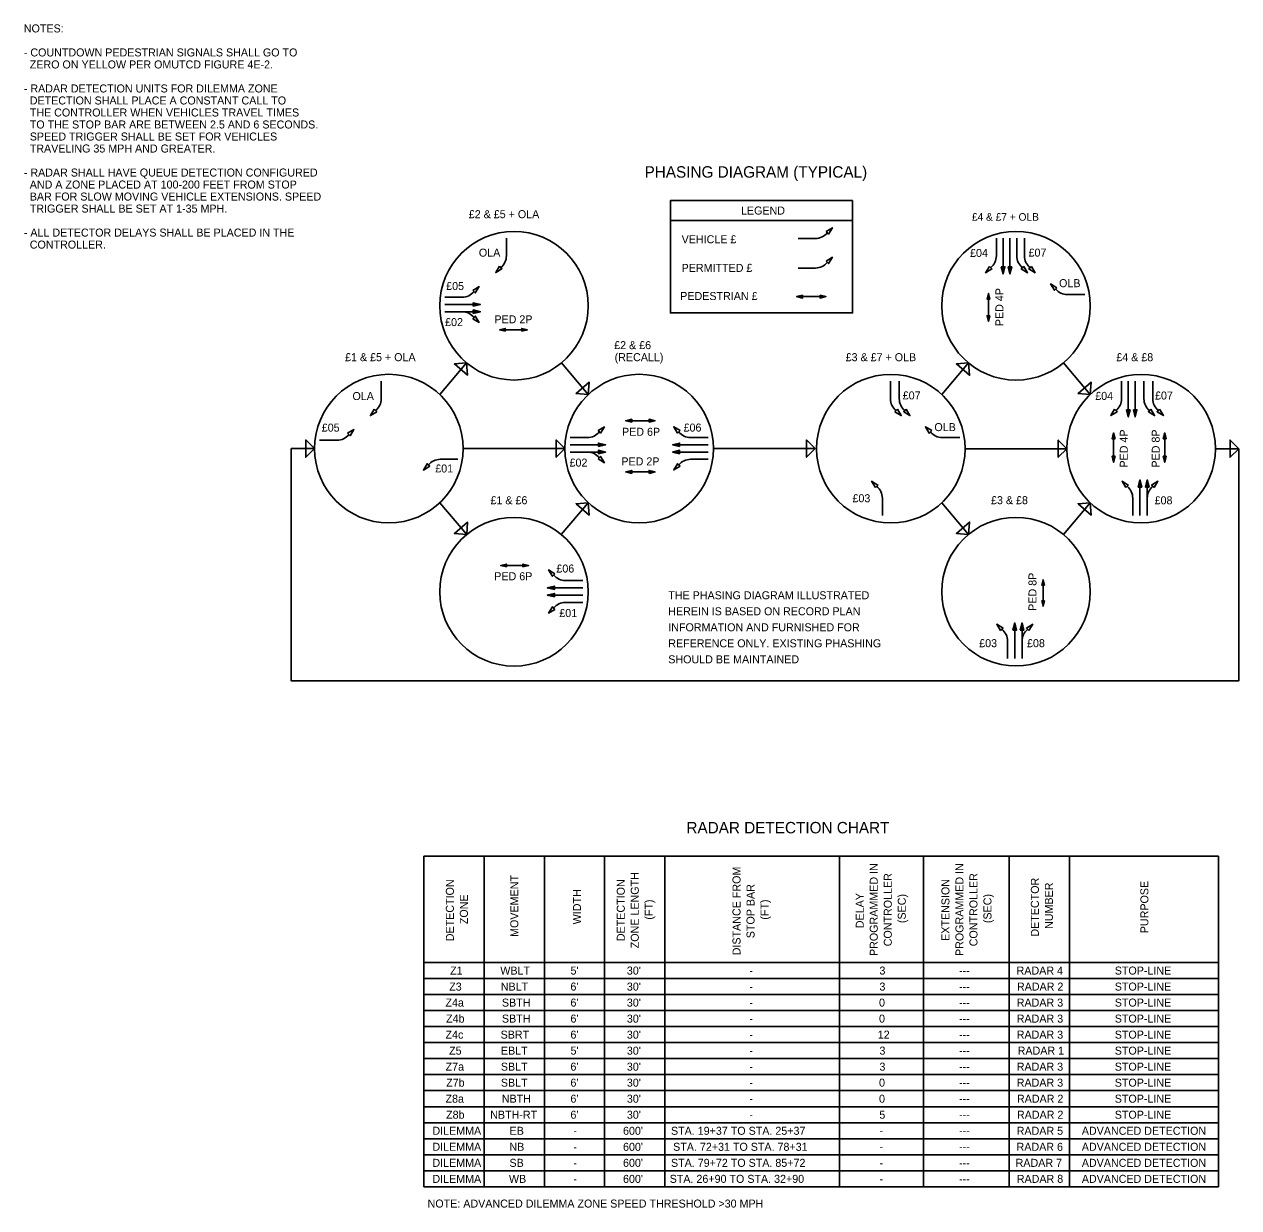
# Model space of a CAD drawing. Extents: x 680 to 2132, y 0 to 656.
# Drawn here: x 1377.8 to 1802.7, y 81 to 494.9 of the extents above; entities that cross this region are included whole.
import ezdxf

# ---------------------------------------------------------------- set-up
doc = ezdxf.new("R2010")
doc.units = 0
for name, color, linetype in [('SH_Data', 7, 'Continuous'), ('SH_Text', 7, 'Continuous'), ('ST_Text', 7, 'Continuous')]:
    doc.layers.add(name, color=color, linetype=linetype)

msp = doc.modelspace()

# ---------------------------------------------------------------- linework, layer by layer
at = {"layer": 'SH_Data'}
for p, q in [((1603.79, 426.28), (1667.83, 426.28)), ((1546.48, 420.09), (1546.48, 413.98)), ((1648.51, 420.01), (1654.62, 420.01)), ((1717.88, 420.06), (1717.88, 413.95)), ((1720.22, 407.61), (1720.22, 420.06)), ((1722.63, 407.61), (1722.63, 420.06)), ((1725.04, 420.06), (1725.04, 413.95)), ((1727.7, 420.06), (1727.7, 413.95)), ((1648.51, 409.67), (1654.62, 409.67)), ((1524.93, 399.45), (1531.04, 399.45)), ((1658.28, 399.71), (1648.02, 399.71)), ((1715.16, 391.03), (1715.16, 400.78)), ((1748.85, 400.36), (1742.74, 400.36)), ((1537.38, 396.92), (1524.93, 396.92)), ((1524.93, 394.38), (1531.04, 394.38)), ((1537.38, 394.38), (1524.93, 394.38)), ((1544.09, 388.03), (1553.84, 388.03)), ((1532.57, 376.48), (1523.14, 365.44)), ((1575.14, 365.44), (1565.71, 376.48)), ((1708.16, 376.46), (1698.76, 365.45)), ((1750.75, 365.44), (1741.33, 376.46)), ((1502.68, 370.09), (1502.68, 363.98)), ((1680.84, 370.09), (1680.84, 363.98)), ((1683.92, 370.09), (1683.92, 363.98)), ((1761.69, 370.09), (1761.69, 363.98)), ((1764.03, 357.63), (1764.03, 370.09)), ((1766.43, 357.63), (1766.43, 370.09)), ((1769.51, 370.09), (1769.51, 363.98)), ((1772.59, 370.09), (1772.59, 363.98)), ((1588.23, 356.25), (1598.49, 356.25)), ((1481.12, 349.46), (1487.23, 349.46)), ((1568.73, 350.39), (1574.84, 350.39)), ((1617.04, 350.39), (1610.93, 350.39)), ((1705.07, 350.39), (1698.96, 350.39)), ((1758.91, 341.75), (1758.91, 352.02)), ((1776.81, 341.75), (1776.81, 352.02)), ((1566.95, 346.51), (1531.33, 346.51)), ((1581.19, 347.85), (1568.73, 347.85)), ((1581.19, 345.32), (1568.73, 345.32)), ((1568.73, 345.32), (1574.84, 345.31)), ((1604.59, 347.85), (1617.04, 347.85)), ((1604.59, 345.32), (1617.04, 345.32)), ((1654.55, 346.51), (1618.93, 346.51)), ((1742.56, 346.5), (1706.96, 346.5)), ((1529.44, 342.78), (1523.33, 342.78)), ((1617.04, 342.78), (1610.93, 342.78)), ((1588.23, 338.36), (1598.49, 338.36)), ((1768.13, 335.55), (1768.13, 323.09)), ((1770.66, 335.55), (1770.66, 323.09)), ((1532.59, 316.5), (1523.14, 327.57)), ((1575.14, 327.57), (1565.69, 316.5)), ((1678, 323.09), (1678, 329.2)), ((1708.18, 316.52), (1698.76, 327.56)), ((1750.75, 327.56), (1741.32, 316.52)), ((1765.59, 323.09), (1765.59, 329.2)), ((1544.48, 305.64), (1554.23, 305.64)), ((1560.78, 297.81), (1573.24, 297.81)), ((1573.24, 300.35), (1567.13, 300.35)), ((1734.23, 291.39), (1734.23, 300.65)), ((1560.78, 295.27), (1573.24, 295.27)), ((1573.24, 292.74), (1567.13, 292.74)), ((1724.32, 285.54), (1724.32, 273.08)), ((1726.86, 285.54), (1726.86, 273.08)), ((1721.79, 273.08), (1721.79, 279.19)), ((1726.86, 279.05), (1726.86, 279.19))]:
    msp.add_line(p, q, dxfattribs=at)
for points in [[(1667.6, 433.28), (1603.83, 433.28), (1603.83, 393.95), (1667.6, 393.95)], [(1658.31, 422.43), (1660.52, 423.76), (1659.19, 421.55)], [(1658.31, 412.09), (1660.52, 413.42), (1659.19, 411.21)], [(1544.06, 410.29), (1542.73, 408.08), (1544.94, 409.41)], [(1715.46, 410.26), (1714.14, 408.05), (1716.35, 409.38)], [(1719.6, 410.11), (1720.22, 407.61), (1720.85, 410.11)], [(1722, 410.11), (1722.63, 407.61), (1723.26, 410.11)], [(1727.46, 410.26), (1728.78, 408.05), (1726.57, 409.38)], [(1730.12, 410.26), (1731.45, 408.05), (1729.24, 409.38)], [(1739.05, 402.78), (1736.84, 404.11), (1738.17, 401.9)], [(1534.73, 401.87), (1536.94, 403.2), (1535.61, 400.99)], [(1650.1, 400.23), (1648.02, 399.71), (1650.1, 399.19)], [(1656.2, 400.23), (1658.28, 399.71), (1656.2, 399.19)], [(1715.65, 398.8), (1715.16, 400.78), (1714.66, 398.8)], [(1534.88, 396.29), (1537.38, 396.92), (1534.88, 397.54)], [(1534.72, 391.96), (1536.94, 390.63), (1535.61, 392.84)], [(1534.88, 393.76), (1537.38, 394.38), (1534.88, 395.01)], [(1715.65, 393.01), (1715.16, 391.03), (1714.66, 393.01)], [(1546.07, 387.54), (1544.09, 388.03), (1546.07, 388.53)], [(1551.86, 387.54), (1553.84, 388.03), (1551.86, 388.53)], [(1532.57, 376.48), (1528.29, 376.14), (1532.9, 372.21)], [(1708.16, 376.46), (1703.89, 376.12), (1708.5, 372.19)], [(1575.14, 365.44), (1570.86, 365.78), (1575.47, 369.72)], [(1750.75, 365.44), (1746.47, 365.77), (1751.08, 369.71)], [(1500.26, 360.29), (1498.93, 358.08), (1501.14, 359.41)], [(1683.26, 360.29), (1684.59, 358.08), (1682.38, 359.41)], [(1686.34, 360.29), (1687.66, 358.08), (1685.46, 359.41)], [(1759.26, 360.29), (1757.94, 358.08), (1760.15, 359.41)], [(1763.4, 360.13), (1764.03, 357.63), (1764.65, 360.13)], [(1765.81, 360.13), (1766.43, 357.63), (1767.06, 360.13)], [(1771.93, 360.29), (1773.25, 358.08), (1771.05, 359.41)], [(1775.01, 360.29), (1776.33, 358.08), (1774.12, 359.41)], [(1490.92, 351.88), (1493.14, 353.2), (1491.81, 350.99)], [(1578.53, 352.81), (1580.74, 354.13), (1579.41, 351.93)], [(1590.31, 355.73), (1588.23, 356.25), (1590.31, 356.77)], [(1596.41, 355.73), (1598.49, 356.25), (1596.41, 356.77)], [(1607.25, 352.81), (1605.03, 354.14), (1606.36, 351.93)], [(1695.27, 352.81), (1693.06, 354.13), (1694.39, 351.92)], [(1479.34, 346.51), (1476.31, 349.54), (1476.31, 343.48)], [(1566.95, 346.51), (1563.92, 349.54), (1563.92, 343.48)], [(1578.69, 347.23), (1581.19, 347.85), (1578.69, 348.48)], [(1607.09, 347.23), (1604.59, 347.85), (1607.09, 348.48)], [(1654.55, 346.51), (1651.52, 349.54), (1651.52, 343.48)], [(1742.56, 346.5), (1739.53, 349.53), (1739.53, 343.47)], [(1759.43, 349.94), (1758.91, 352.02), (1758.39, 349.94)], [(1777.33, 349.94), (1776.81, 352.02), (1776.29, 349.94)], [(1802.66, 346.5), (1799.63, 349.53), (1799.63, 343.47)], [(1578.69, 344.69), (1581.19, 345.32), (1578.69, 345.94)], [(1607.09, 344.69), (1604.59, 345.32), (1607.09, 345.94)], [(1519.64, 340.36), (1517.43, 339.03), (1518.76, 341.24)], [(1578.53, 342.89), (1580.74, 341.57), (1579.41, 343.78)], [(1607.25, 340.36), (1605.03, 339.04), (1606.36, 341.24)], [(1759.43, 343.84), (1758.91, 341.75), (1758.39, 343.84)], [(1777.33, 343.84), (1776.81, 341.75), (1776.29, 343.84)], [(1590.31, 337.84), (1588.23, 338.36), (1590.31, 338.88)], [(1596.41, 337.84), (1598.49, 338.36), (1596.41, 338.88)], [(1675.58, 332.89), (1674.26, 335.1), (1676.47, 333.77)], [(1763.17, 332.89), (1761.84, 335.1), (1764.05, 333.77)], [(1767.5, 333.05), (1768.13, 335.55), (1768.75, 333.05)], [(1770.04, 333.05), (1770.66, 335.55), (1771.29, 333.05)], [(1773.08, 332.89), (1774.41, 335.1), (1772.2, 333.77)], [(1575.14, 327.57), (1570.86, 327.23), (1575.47, 323.29)], [(1750.75, 327.56), (1746.47, 327.23), (1751.08, 323.29)], [(1532.59, 316.5), (1528.31, 316.84), (1532.92, 320.78)], [(1708.18, 316.52), (1703.91, 316.86), (1708.52, 320.8)], [(1546.46, 305.15), (1544.48, 305.64), (1546.46, 306.14)], [(1552.25, 305.15), (1554.23, 305.64), (1552.25, 306.14)], [(1563.44, 302.77), (1561.23, 304.09), (1562.56, 301.89)], [(1563.28, 297.19), (1560.78, 297.81), (1563.28, 298.44)], [(1734.7, 298.77), (1734.23, 300.65), (1733.76, 298.77)], [(1563.28, 294.65), (1560.78, 295.27), (1563.28, 295.9)], [(1734.7, 293.27), (1734.23, 291.39), (1733.76, 293.27)], [(1563.44, 290.31), (1561.23, 288.99), (1562.56, 291.2)], [(1719.37, 282.88), (1718.04, 285.09), (1720.25, 283.76)], [(1723.7, 283.04), (1724.32, 285.54), (1724.95, 283.04)], [(1726.23, 283.04), (1726.86, 285.54), (1727.48, 283.04)], [(1729.28, 282.88), (1730.6, 285.09), (1728.4, 283.76)]]:
    msp.add_lwpolyline(points, close=True, dxfattribs=at)
msp.add_lwpolyline([(1794.54, 346.5), (1802.66, 346.5), (1802.66, 265.28), (1479.34, 265.28), (1471.22, 265.28), (1471.22, 346.51), (1479.34, 346.51)], dxfattribs=at)
for centre in [(1549.14, 396.5), (1724.75, 396.48), (1505.34, 346.51), (1592.94, 346.51), (1680.96, 346.5), (1768.55, 346.5), (1549.14, 296.46), (1724.75, 296.49)]:
    msp.add_circle(centre, 25.99, dxfattribs=at)
for centre, start, end in [((1654.62, 425.31), 270.0129, 321.2136), ((1541.18, 413.98), 308.7993, 0), ((1712.58, 413.95), 308.7993, 0), ((1730.34, 413.95), 180, 231.2007), ((1733, 413.95), 180, 231.2007), ((1654.62, 414.97), 270, 321.2007), ((1531.04, 404.75), 270, 321.2007), ((1742.74, 405.66), 218.7864, 269.9871), ((1531.04, 389.08), 38.7864, 89.9871), ((1497.38, 363.98), 308.7993, 0), ((1686.14, 363.98), 180, 231.2007), ((1689.22, 363.98), 180, 231.2007), ((1756.38, 363.98), 308.7993, 0), ((1774.81, 363.98), 180, 231.2007), ((1777.89, 363.98), 180, 231.2007), ((1487.23, 354.76), 270, 321.2007), ((1574.84, 355.69), 270, 321.2007), ((1610.94, 355.69), 218.7864, 269.9871), ((1698.96, 355.69), 218.7864, 269.9871), ((1574.84, 340.01), 38.7864, 89.9871), ((1523.33, 337.48), 90.0129, 141.2136), ((1610.93, 337.48), 90, 141.2007), ((1672.7, 329.2), 360, 51.2007), ((1760.29, 329.2), 360, 51.2007), ((1775.96, 329.2), 128.7993, 178.779), ((1567.13, 305.65), 218.7864, 269.9871), ((1567.13, 287.44), 90.0129, 141.2136), ((1716.49, 279.19), 360, 51.2007), ((1732.16, 279.19), 128.7993, 180)]:
    msp.add_arc(centre, 5.3, start, end, dxfattribs=at)
at = {"layer": 'ST_Text'}
for p, q in [((1517.6, 204.01), (1795.54, 204.01)), ((1517.6, 204.01), (1517.6, 88.34)), ((1538.69, 204.01), (1538.69, 88.34)), ((1559.77, 204.01), (1559.77, 88.34)), ((1580.85, 204.01), (1580.85, 110.77)), ((1580.85, 204.01), (1580.85, 88.34)), ((1601.93, 204.01), (1601.93, 88.34)), ((1663.02, 204.01), (1663.02, 88.34)), ((1692.43, 204.01), (1692.43, 88.34)), ((1722.41, 204.01), (1722.41, 88.34)), ((1743.49, 204.01), (1743.49, 88.34)), ((1795.54, 204.01), (1795.54, 88.34)), ((1517.6, 166.8), (1795.54, 166.8)), ((1517.6, 161.2), (1795.54, 161.2)), ((1517.6, 155.6), (1795.54, 155.6)), ((1517.6, 150), (1795.54, 150)), ((1517.6, 144.4), (1795.54, 144.4)), ((1517.6, 138.8), (1795.54, 138.8)), ((1517.6, 133.2), (1795.54, 133.2)), ((1517.6, 127.6), (1795.54, 127.6)), ((1517.6, 121.98), (1795.54, 121.98)), ((1517.6, 116.38), (1795.54, 116.38)), ((1517.6, 110.77), (1795.54, 110.77)), ((1517.6, 105.17), (1795.54, 105.17)), ((1517.6, 99.55), (1795.54, 99.55)), ((1517.6, 93.95), (1795.54, 93.95)), ((1517.6, 88.34), (1795.54, 88.34))]:
    msp.add_line(p, q, dxfattribs=at)

# ---------------------------------------------------------------- texts
at = {"layer": 'SH_Text'}
for s, height, p in [('NOTES:', 2.8, (1377.66, 492.07)), ('- COUNTDOWN PEDESTRIAN SIGNALS SHALL GO TO ', 2.8, (1377.66, 483.67)), ('  ZERO ON YELLOW PER OMUTCD FIGURE 4E-2.', 2.8, (1377.66, 479.47)), ('- RADAR DETECTION UNITS FOR DILEMMA ZONE ', 2.8, (1377.66, 471.07)), ('  DETECTION SHALL PLACE A CONSTANT CALL TO ', 2.8, (1377.66, 466.87)), ('  THE CONTROLLER WHEN VEHICLES TRAVEL TIMES ', 2.8, (1377.66, 462.67)), ('  TO THE STOP BAR ARE BETWEEN 2.5 AND 6 SECONDS. ', 2.8, (1377.66, 458.47)), ('  SPEED TRIGGER SHALL BE SET FOR VEHICLES ', 2.8, (1377.66, 454.27)), ('  TRAVELING 35 MPH AND GREATER.', 2.8, (1377.66, 450.07)), ('- RADAR SHALL HAVE QUEUE DETECTION CONFIGURED ', 2.8, (1377.66, 441.67)), ('PHASING DIAGRAM (TYPICAL)', 4, (1594.82, 441.28)), ('  AND A ZONE PLACED AT 100-200 FEET FROM STOP ', 2.8, (1377.66, 437.47)), ('  BAR FOR SLOW MOVING VEHICLE EXTENSIONS. SPEED ', 2.8, (1377.66, 433.27)), ('  TRIGGER SHALL BE SET AT 1-35 MPH.', 2.8, (1377.66, 429.07)), ('£2 & £5 + OLA', 2.8, (1533.32, 427.1)), ('LEGEND', 2.8, (1628.55, 428.38)), ('£4 & £7 + OLB', 2.66, (1709.33, 426.22)), ('- ALL DETECTOR DELAYS SHALL BE PLACED IN THE ', 2.8, (1377.66, 420.67)), ('VEHICLE £', 2.8, (1607.78, 418.33)), ('  CONTROLLER.', 2.8, (1377.66, 416.47)), ('OLA', 2.8, (1536.85, 413.65)), ('£04', 2.8, (1708.68, 413.54)), ('£07', 2.8, (1729.14, 413.66)), ('PERMITTED £', 2.8, (1607.78, 408.33)), ('£05', 2.8, (1525.4, 401.98)), ('OLB', 2.8, (1739.82, 402.98)), ('PEDESTRIAN £', 2.8, (1607.29, 398.49)), ('£02', 2.8, (1525.04, 389.36)), ('PED 2P', 2.8, (1542.27, 390.33)), ('£2 & £6', 2.8, (1584.19, 381.3)), ('£1 & £5 + OLA', 2.8, (1490.05, 377.1)), ('(RECALL)', 2.8, (1584.35, 377.1)), ('£3 & £7 + OLB', 2.8, (1665.16, 377.09)), ('£4 & £8', 2.8, (1759.84, 377.09)), ('OLA', 2.8, (1492.63, 363.5)), ('£07', 2.8, (1685.13, 363.73)), ('£04', 2.8, (1752.48, 363.56)), ('£07', 2.8, (1773.39, 363.69)), ('£05', 2.8, (1481.89, 352.46)), ('PED 6P', 2.8, (1586.93, 351)), ('£06', 2.8, (1608.46, 352.48)), ('OLB', 2.8, (1696.21, 352.64)), ('£01', 2.8, (1521.59, 338.17)), ('£02', 2.8, (1568.57, 340.23)), ('PED 2P', 2.8, (1586.7, 340.65)), ('£1 & £6', 2.8, (1540.92, 327.06)), ('£03', 2.8, (1667.55, 327.76)), ('£3 & £8', 2.8, (1716.02, 327.09)), ('£08', 2.8, (1773.25, 327.03)), ('£06', 2.8, (1563.97, 303.18)), ('PED 6P', 2.8, (1542.24, 300.48)), ('THE PHASING DIAGRAM ILLUSTRATED ', 2.8, (1603.11, 293.83)), ('£01', 2.8, (1564.99, 287.61)), ('HEREIN IS BASED ON RECORD PLAN ', 2.8, (1603.11, 288.23)), ('INFORMATION AND FURNISHED FOR ', 2.8, (1603.11, 282.63)), ('REFERENCE ONLY. EXISTING PHASHING ', 2.8, (1603.11, 277.03)), ('£03', 2.8, (1711.87, 277.08)), ('£08', 2.8, (1728.61, 277.08)), ('SHOULD BE MAINTAINED', 2.8, (1603.11, 271.43)), ('RADAR DETECTION CHART', 4, (1609.46, 211.96))]:
    msp.add_text(s, height=height, dxfattribs=at).set_placement(p)
for s, p in [('PED 4P', (1720.34, 389.34)), ('PED 4P', (1763.86, 339.89)), ('PED 8P', (1775.03, 339.89)), ('PED 8P', (1731.92, 289.8))]:
    msp.add_text(s, height=2.8, rotation=90, dxfattribs=at).set_placement(p)
at = {"layer": 'ST_Text'}
for s, p in [('DISTANCE FROM', (1628.38, 169.32)), ('PROGRAMMED IN', (1676.39, 169.07)), ('PROGRAMMED IN', (1706.37, 169.07)), ('DETECTION', (1528.1, 174.24)), ('MOVEMENT', (1550.65, 175.75)), ('DETECTION ', (1587.89, 174.27)), ('ZONE LENGTH', (1592.79, 171.77)), ('CONTROLLER', (1681.29, 172.46)), ('EXTENSION', (1701.47, 174.37)), ('CONTROLLER', (1711.27, 172.46)), ('DETECTOR', (1732.76, 175.85)), ('WIDTH', (1572.57, 180.15)), ('STOP BAR', (1633.28, 175.29)), ('NUMBER', (1737.66, 178.53)), ('PURPOSE', (1771.06, 177.04)), ('ZONE', (1533, 180.21)), ('(FT)', (1597.69, 181.77)), ('(FT)', (1638.18, 181.77)), ('DELAY ', (1671.49, 178.8)), ('(SEC)', (1686.19, 180.57)), ('(SEC)', (1716.17, 180.57))]:
    msp.add_text(s, height=2.8, rotation=90, dxfattribs=at).set_placement(p)
for s, p in [('Z1', (1526.79, 162.58)), ('WBLT', (1544.35, 162.58)), ("5'", (1568.91, 162.58)), ("30'", (1588.62, 162.58)), ('-', (1631.48, 162.58)), ('3', (1676.98, 162.58)), ('---', (1704.84, 162.58)), ('RADAR 4', (1724.96, 162.58)), ('STOP-LINE', (1759.3, 162.58)), ('Z3', (1526.47, 156.98)), ('NBLT', (1544.51, 156.98)), ("6'", (1568.88, 156.98)), ("30'", (1588.62, 156.98)), ('-', (1631.48, 156.98)), ('3', (1676.98, 156.98)), ('---', (1704.84, 156.98)), ('RADAR 2', (1725.09, 156.98)), ('STOP-LINE', (1759.3, 156.98)), ('Z4a', (1525.16, 151.38)), ('SBTH', (1544.91, 151.38)), ("6'", (1568.88, 151.38)), ("30'", (1588.62, 151.38)), ('0', (1676.84, 151.38)), ('RADAR 3', (1725.01, 151.38)), ('STOP-LINE', (1759.3, 151.38)), ('Z4b', (1525.37, 145.78)), ('-', (1631.48, 151.38)), ('---', (1704.84, 151.38)), ('SBTH', (1544.91, 145.78)), ("6'", (1568.88, 145.78)), ("30'", (1588.62, 145.78)), ('-', (1631.48, 145.78)), ('0', (1676.84, 145.78)), ('---', (1704.84, 145.78)), ('RADAR 3', (1725.01, 145.78)), ('STOP-LINE', (1759.3, 145.78)), ('Z4c', (1525.18, 140.18)), ('SBRT', (1544.46, 140.18)), ("6'", (1568.88, 140.18)), ("30'", (1588.62, 140.18)), ('-', (1631.48, 140.18)), ('12', (1676.39, 140.18)), ('---', (1704.84, 140.18)), ('RADAR 3', (1725.01, 140.18)), ('STOP-LINE', (1759.3, 140.18)), ('Z5', (1526.44, 134.58)), ('EBLT', (1544.57, 134.58)), ("5'", (1568.91, 134.58)), ("30'", (1588.62, 134.58)), ('3', (1676.98, 134.58)), ('RADAR 1', (1725.34, 134.58)), ('STOP-LINE', (1759.3, 134.58)), ('Z7a', (1525.2, 128.98)), ('SBLT', (1544.54, 128.98)), ("6'", (1568.88, 128.98)), ("30'", (1588.62, 128.98)), ('-', (1631.48, 134.58)), ('3', (1676.98, 128.98)), ('---', (1704.84, 134.58)), ('RADAR 3', (1725.01, 128.98)), ('STOP-LINE', (1759.3, 128.98)), ('-', (1631.48, 128.98)), ('---', (1704.84, 128.98)), ('Z7b', (1525.41, 123.38)), ('SBLT', (1544.54, 123.38)), ("6'", (1568.88, 123.38)), ("30'", (1588.62, 123.38)), ('-', (1631.48, 123.38)), ('0', (1676.84, 123.38)), ('---', (1704.84, 123.38)), ('RADAR 3', (1725.01, 123.38)), ('STOP-LINE', (1759.3, 123.38)), ('Z8a', (1525.18, 117.77)), ('NBTH', (1544.88, 117.77)), ("6'", (1568.88, 117.77)), ("30'", (1588.62, 117.77)), ('-', (1631.48, 117.77)), ('0', (1676.84, 117.77)), ('---', (1704.84, 117.77)), ('RADAR 2', (1725.09, 117.77)), ('STOP-LINE', (1759.3, 117.78)), ('Z8b', (1525.38, 112.17)), ('NBTH-RT', (1540.82, 112.17)), ("6'", (1568.88, 112.17)), ("30'", (1588.62, 112.17)), ('5', (1676.95, 112.17)), ('RADAR 2', (1725.09, 112.17)), ('STOP-LINE', (1759.3, 112.17)), ('-', (1631.48, 112.17)), ('---', (1704.84, 112.17)), ('DILEMMA', (1520.6, 106.55)), ('EB', (1547.59, 106.55)), ('-', (1569.91, 106.55)), ("600'", (1587.28, 106.55)), ('STA. 19+37 TO STA. 25+37', (1604.05, 106.55)), ('-', (1677.04, 106.55)), ('---', (1704.84, 106.57)), ('RADAR 5', (1724.99, 106.55)), ('ADVANCED DETECTION', (1747.78, 106.55)), ('DILEMMA', (1520.6, 100.95)), ('NB', (1547.53, 100.95)), ('-', (1569.91, 100.94)), ("600'", (1587.28, 100.94)), ('STA. 72+31 TO STA. 78+31', (1604.81, 100.95)), ('-', (1677.04, 100.95)), ('---', (1704.84, 100.97)), ('RADAR 6', (1724.95, 100.95)), ('ADVANCED DETECTION', (1747.78, 100.95)), ('DILEMMA', (1520.6, 95.34)), ('SB', (1547.56, 95.34)), ("600'", (1587.28, 95.34)), ('STA. 79+72 TO STA. 85+72', (1604.05, 95.34)), ('RADAR 7', (1724.62, 95.34)), ('ADVANCED DETECTION', (1747.78, 95.34)), ('-', (1569.91, 95.34)), ('-', (1677.04, 95.34)), ('---', (1704.84, 95.35)), ('DILEMMA', (1520.6, 89.74)), ('WB', (1547.37, 89.74)), ('-', (1569.91, 89.72)), ("600'", (1587.28, 89.72)), ('STA. 26+90 TO STA. 32+90', (1603.6, 89.74)), ('-', (1677.04, 89.74)), ('---', (1704.84, 89.75)), ('RADAR 8', (1725.03, 89.74)), ('ADVANCED DETECTION', (1747.78, 89.74)), ('NOTE: ADVANCED DILEMMA ZONE SPEED THRESHOLD >30 MPH', (1518.92, 81.09))]:
    msp.add_text(s, height=2.8, dxfattribs=at).set_placement(p)

doc.saveas('drawing.dxf')
